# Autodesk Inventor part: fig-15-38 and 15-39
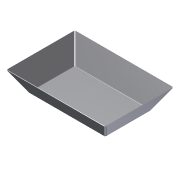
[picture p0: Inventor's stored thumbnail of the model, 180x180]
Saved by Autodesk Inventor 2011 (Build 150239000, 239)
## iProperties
Created: 2007-05
Part Number: fig-15-38 and 15-39
Document SubType Name: Sheet Metal
Designer: Administrator
Density: 1 g/cm^3
Sheet Metal Rule: Default
Author: Administrator
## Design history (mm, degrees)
node "Face1"
  sketch "Sketch1"
    geometry: L1 (-17.365, -15.579)-(32.635, -15.579); L2 (32.635, -15.579)-(32.635, 14.421); L3 (32.635, 14.421)-(-17.365, 14.421); L4 (-17.365, 14.421)-(-17.365, -15.579)
    constraints: 8 end point, 2 parallel, 1 horizontal, 1 perpendicular
    dimensions: "d0" = 30 distance of L3.end L1.start; "d1" = 50 distance of L1.start L1.end
node "Flange1"
body "Solid1"
face "Plate1" dims "Thickness" = 0.3
sketch "Sketch2"
  geometry: L1 (0, 15)-(-30, 15); L2 (-30, 15)-(-30, 0); 2 other entities
  constraints: 4 end point, 4 other
face "Plate2" dims "d3" = 0.3 (= BendReliefWidth), "d4" = 0.15 (= BendReliefDepth), "d5" = 0.6 (= MinimumRemnant), "d6" = 0.3 (= BendRadius), "d7" = 15, "d8" = 60 deg, "d9" = 0.3 (= BendRadius), "d10" = 1.2 (= CornerReliefSize), "d11" = 0.5, "d12" = 0.3 (= JacobiRadiusSize), "SeamGap" = 0.01, "Thickness" = 0.3
bend "Bend1" dims "d3" = 0.3 (= BendReliefWidth), "d4" = 0.15 (= BendReliefDepth), "d5" = 0.6 (= MinimumRemnant), "d6" = 0.3 (= BendRadius), "d7" = 15, "d8" = 60 deg, "d9" = 0.3 (= BendRadius), "SeamGap" = 0.01, "Thickness" = 0.3
feature "Corner1" dims "d7" = 15, "d8" = 60 deg, "d10" = 1.2 (= CornerReliefSize), "d11" = 0.5, "d12" = 0.3 (= JacobiRadiusSize)
other parameters: "BendRadius" = 0.3 (= Thickness), "BendReliefWidth" = 0.3 (= Thickness), "BendReliefDepth" = 0.15 (= 0.5 x Thickness), "CornerReliefSize" = 1.2 (= 4 x Thickness), "MinimumRemnant" = 0.6 (= 2 x Thickness), "TransitionRadius" = 0.3 (= BendRadius), "JacobiRadiusSize" = 0.3 (= Thickness), "d2" = 0.3 (= BendRadius), "GapSize" = 0.3 (= Thickness)
